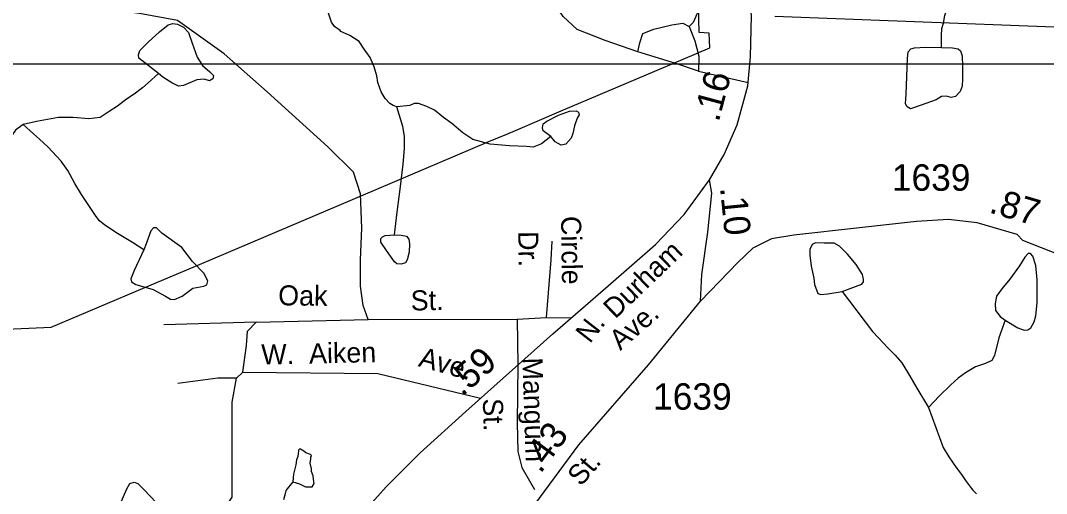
# Model space of a CAD drawing. Extents: x 2056842 to 2160602, y 826753 to 1016856.
# Drawn here: x 2090814 to 2095668, y 864586 to 866824 of the extents above; entities that cross this region are included whole.
import ezdxf

# ---------------------------------------------------------------- set-up
doc = ezdxf.new("R2010")
doc.units = 0
for name, color, linetype in [('Exist Boundary Political City Limit New', 7, 'Continuous'), ('Exist Hydrographic Creek Single Shore', 7, 'Continuous'), ('Exist Hydrographic Misc Water Feature', 7, 'Continuous'), ('Exist Road Non-System Type 51', 7, 'Continuous'), ('Exist Road Non-System Type 51 Label', 7, 'Continuous'), ('Exist Road Primary US Attributed', 7, 'Continuous'), ('Exist Road Primary US Label', 7, 'Continuous'), ('Exist Road Primary US Mileage Hundredths English Label', 7, 'Continuous'), ('Exist Road Secondary Mileage Hundredths English Label', 7, 'Continuous'), ('Exist Road Secondary Type 51 Attributed', 7, 'Continuous'), ('Exist Road Secondary Type 51 Label', 7, 'Continuous'), ('Exist Road Secondary Type 51 Number Label', 7, 'Continuous'), ('Map Preparation Boundary City Limit Buffer Line', 7, 'Continuous'), ('Scratch_Level_6', 7, 'Continuous')]:
    doc.layers.add(name, color=color, linetype=linetype)

msp = doc.modelspace()

# ---------------------------------------------------------------- linework, layer by layer
at = {"layer": 'Exist Boundary Political City Limit New'}
for points in [[(2090320.6, 865345.3), (2090958.1, 865372.4), (2091361.1, 865543.2), (2091671.4, 865674.6), (2092500, 866025.6), (2093030.2, 866250.8), (2093114.1, 866286.4), (2093155, 866303.8), (2093371.6, 866395.8), (2093866.6, 866606), (2093874.8, 866609.4), (2093886.4, 866614.4), (2094074.5, 866694.3), (2094071.5, 866763.2), (2094025.5, 866766.9), (2094021.9, 866891.5)], [(2094383.1, 866844.7), (2095704, 866794.2)]]:
    msp.add_lwpolyline(points, dxfattribs=at)
at = {"layer": 'Exist Hydrographic Creek Single Shore'}
for points in [[(2095170.7, 866696.3), (2095171.1, 866752.9), (2095173.2, 866785.1), (2095181, 866811.1), (2095186.9, 866847.1), (2095206.6, 866907), (2095216.4, 866935.2), (2095258.3, 866997.4), (2095282.3, 867031.5), (2095310.4, 867067.5), (2095335.8, 867103.6), (2095395.7, 867179.8), (2095415.3, 867223.9), (2095427.6, 867274), (2095437.1, 867316)], [(2092594.5, 866414.5), (2092576.4, 866421), (2092560.6, 866430.8), (2092538.3, 866454.9), (2092520.2, 866486.7), (2092504.2, 866530.6), (2092500.1, 866562.5), (2092487.6, 866604.5), (2092467.7, 866648.5), (2092439.6, 866688.5), (2092415.8, 866724.2), (2092371.6, 866752), (2092329.5, 866772.2), (2092325.4, 866776.1), (2092299.4, 866795.8), (2092285.2, 866815.7), (2092269, 866863.7)], [(2095170.7, 866696.3), (2095223, 866694.6), (2095250.9, 866689.7), (2095261.8, 866680), (2095269.1, 866655.7), (2095270.4, 866605.8), (2095271.6, 866547.5), (2095269.1, 866513.4), (2095259.4, 866487.9), (2095237.5, 866463.5), (2095216.9, 866459.9), (2095195, 866466), (2095170.7, 866464.8), (2095146.4, 866447.7), (2095074.7, 866423.4), (2095024.8, 866406.4), (2095009, 866414.9), (2095001.7, 866429.5), (2095004.2, 866474.5), (2095007.8, 866558.4), (2095010.2, 866646), (2095013.9, 866675.2), (2095026, 866689.7), (2095044.3, 866694.6), (2095096.5, 866697), (2095170.7, 866696.3)], [(2091466.5, 866572.6), (2091418.3, 866529.3), (2091390.4, 866505.1), (2091350.6, 866475), (2091314.7, 866450.9), (2091272.9, 866418.7), (2091232.7, 866392.6), (2091190.7, 866364.5), (2091136.7, 866358.3), (2091062.9, 866364.6), (2090993, 866364.6), (2090889.3, 866345.8), (2090826.8, 866332.1)], [(2090826.8, 866332.1), (2090790.5, 866304.6), (2090773.1, 866279.6), (2090763.1, 866253.3), (2090733.6, 866217.1), (2090693.4, 866192.8), (2090649.5, 866184.8), (2090601.5, 866174.7), (2090549.5, 866160.6), (2090485.7, 866142)], [(2095472.7, 865405.6), (2095532.2, 865369.4), (2095562.6, 865358.5), (2095579.6, 865360.9), (2095594.2, 865369.4), (2095610, 865398.6), (2095618.5, 865426.6), (2095623.4, 865488.6), (2095624.6, 865596.8), (2095617.3, 865664.9), (2095603.9, 865708.7), (2095591.8, 865720.9), (2095580.8, 865722.1), (2095566.3, 865703.8), (2095540.7, 865662.5), (2095494.5, 865599.3), (2095456.9, 865554.3), (2095431.3, 865519), (2095425.3, 865484.9), (2095427.7, 865452.1), (2095449.6, 865422.9), (2095472.7, 865405.6)], [(2094702.1, 865541.4), (2094845.3, 865352.1), (2094873.4, 865322.3), (2094917.9, 865274.6), (2094952.1, 865240.5), (2094983.9, 865204.4), (2095020.2, 865144.6), (2095054.5, 865085), (2095109.2, 864992.2)], [(2095472.7, 865405.6), (2095443.5, 865321.7), (2095422.8, 865239), (2095409.5, 865214.7), (2095379.1, 865201.3), (2095331.7, 865185.5), (2095285.5, 865157.6), (2095250.2, 865132), (2095215, 865100.4), (2095160.3, 865046.9), (2095109.2, 864992.2)], [(2095109.2, 864992.2), (2095179.3, 864803.2), (2095205.6, 864759.5), (2095241.5, 864709.4), (2095265.5, 864675.7), (2095285.5, 864647.9), (2095299.7, 864627.9), (2095314.1, 864609.9)], [(2095314.1, 864609.9), (2095320, 864601.7), (2095337.8, 864584.4)]]:
    msp.add_lwpolyline(points, dxfattribs=at)
at = {"layer": 'Exist Hydrographic Misc Water Feature'}
msp.add_line((2092102.1, 864641.5), (2092069.7, 864600.9), dxfattribs=at)
for points in [[(2091466.5, 866572.6), (2091374.1, 866645.1), (2091371.6, 866661.4), (2091377.8, 866681.4), (2091417.8, 866721.4), (2091471.5, 866770.1), (2091511.5, 866802.6), (2091534, 866810.1), (2091556.5, 866806.4), (2091585.2, 866792.6), (2091607.7, 866766.4), (2091626.4, 866716.4), (2091650.2, 866650.1), (2091673.9, 866610.1), (2091708.9, 866581.4), (2091726.4, 866563.9), (2091723.9, 866547.6), (2091707.7, 866537.6), (2091682.7, 866546.4), (2091647.7, 866542.6), (2091585.2, 866516.3), (2091561.5, 866512.6), (2091529, 866528.9), (2091486.5, 866555.1), (2091466.5, 866572.6)], [(2092582.4, 865810.4), (2092595.7, 865917.4), (2092610.3, 866025.6), (2092623.7, 866144.6), (2092629.8, 866217.5), (2092631, 866277.1), (2092622.5, 866322.1), (2092594.5, 866414.5)], [(2093322.6, 866274.7), (2093278.8, 866239.4), (2093239.1, 866224.9), (2093207.1, 866226.8), (2093127, 866230.5), (2093035.1, 866238.3), (2092953.1, 866260.1), (2092906.7, 866291.8), (2092854.7, 866335.9), (2092814.5, 866365.5), (2092772.6, 866399.5), (2092736.5, 866417.5), (2092696.4, 866431.3), (2092676.3, 866431.1), (2092656.4, 866421.1), (2092594.5, 866414.5)], [(2093322.6, 866274.7), (2093287.3, 866301.4), (2093283.7, 866316), (2093286.1, 866334.3), (2093304.3, 866347.7), (2093359, 866375.6), (2093411.3, 866395.1), (2093442.9, 866396.3), (2093453.8, 866390.2), (2093457.5, 866376.8), (2093447.7, 866361), (2093434.4, 866325.8), (2093427.1, 866289.3), (2093419.8, 866267.4), (2093393.1, 866238.2), (2093372.4, 866234.6), (2093343.2, 866250.4), (2093322.6, 866274.7)], [(2091396.5, 865739.1), (2091342.8, 865772.9), (2091272.8, 865815.4), (2091212.9, 865855.4), (2091186.6, 865876.6), (2091172.2, 865896.6), (2091140.2, 865944.5), (2091102.1, 866000.2), (2091069.9, 866052.1), (2091037.7, 866114.3), (2091005.5, 866158), (2090943.2, 866225.9), (2090903.4, 866261.6), (2090874.9, 866287.4), (2090826.8, 866332.1)], [(2091396.5, 865739.1), (2091351.6, 865641.6), (2091335.3, 865601.6), (2091339.1, 865587.8), (2091359.1, 865574.1), (2091441.5, 865551.6), (2091499, 865520.3), (2091522.7, 865505.3), (2091541.5, 865504.1), (2091577.7, 865520.3), (2091628.9, 865557.8), (2091681.4, 865566.6), (2091695.2, 865572.8), (2091700.2, 865591.6), (2091681.4, 865627.8), (2091627.7, 865684.1), (2091576.5, 865750.4), (2091482.8, 865817.9), (2091456.5, 865842.9), (2091442.8, 865842.9), (2091430.3, 865829.1), (2091407.8, 865767.9), (2091396.5, 865739.1)], [(2092582.4, 865810.4), (2092615.2, 865807.9), (2092639.5, 865803.1), (2092650.4, 865789.7), (2092654.1, 865767.8), (2092652.9, 865727.7), (2092643.1, 865691.2), (2092634.6, 865676.6), (2092614, 865671.7), (2092594.5, 865673), (2092582.4, 865682.7), (2092545.9, 865736.2), (2092519.2, 865775.1), (2092517.9, 865792.1), (2092526.4, 865800.6), (2092538.6, 865806.7), (2092582.4, 865810.4)], [(2094702.1, 865541.4), (2094764.1, 865565.7), (2094794.5, 865576.6), (2094801.7, 865587.6), (2094803, 865598.5), (2094796.9, 865621.6), (2094767.7, 865669.1), (2094726.4, 865717.7), (2094688.7, 865756.6), (2094663.2, 865770), (2094617, 865770), (2094575.7, 865772.4), (2094559.9, 865763.9), (2094547.7, 865740.8), (2094548.9, 865714.1), (2094555, 865661.8), (2094567.2, 865604.6), (2094570.8, 865575.4), (2094586.6, 865532.9), (2094601.2, 865526.8), (2094634, 865530.4), (2094702.1, 865541.4)], [(2092102.1, 864641.5), (2092134.1, 864631.7), (2092146.2, 864625.9), (2092162.2, 864617.7), (2092174.3, 864617.9), (2092194.2, 864617.8), (2092198.1, 864625.7), (2092202.4, 864634), (2092202, 864641.8), (2092198.1, 864669.9), (2092190.1, 864689.8), (2092189.9, 864702), (2092183.9, 864729.7), (2092187.6, 864749.8), (2092187.8, 864757.9), (2092189.9, 864765.7), (2092186, 864769.9), (2092163.8, 864777.7), (2092153.8, 864785.8), (2092137.6, 864795.6), (2092133.7, 864795.7), (2092129.6, 864791.5), (2092129.4, 864787.9), (2092127.7, 864775.5), (2092125.9, 864761.6), (2092119.7, 864745.4), (2092115.9, 864721.8), (2092106, 864677.4), (2092102.1, 864641.5)], [(2091385, 864514), (2091307.3, 864511.3), (2091288.9, 864515.3), (2091283.6, 864521.9), (2091284.9, 864535.1), (2091316.5, 864608.9), (2091331, 864632.6), (2091350.8, 864639.2), (2091367.9, 864633.9), (2091398.2, 864603.6), (2091454.9, 864543), (2091457.5, 864527.2), (2091445.7, 864519.2), (2091418, 864516.6), (2091385, 864514)], [(2092069.7, 864600.9), (2092067.7, 864591), (2092058.2, 864556.8)]]:
    msp.add_lwpolyline(points, dxfattribs=at)
at = {"layer": 'Exist Road Non-System Type 51'}
for p, q in [((2094020.9, 866584.5), (2094256.2, 866530.3)), ((2091928.4, 865397), (2091492.3, 865384.5)), ((2091928.4, 865397), (2092458.4, 865409.4)), ((2092458.4, 865409.4), (2093163.2, 865410.5)), ((2093163.2, 865410.5), (2093302.4, 865418.8)), ((2093163.2, 865410.5), (2093166.7, 865194.5)), ((2093302.4, 865418.8), (2093419.7, 865417.4)), ((2091835, 865130.9), (2091866.1, 865160))]:
    msp.add_line(p, q, dxfattribs=at)
for points in [[(2093733.9, 866675.8), (2093580, 866729), (2093447, 866780.4), (2093380.5, 866843.1), (2093343.5, 866897.3), (2093313, 866944.9), (2093276.9, 867013.3), (2093210.4, 867098.9), (2093130.6, 867245.3), (2093042.3, 867360.3), (2092783.8, 867643.7), (2092717.3, 867698.8), (2092588.1, 867860.4), (2092466.5, 867949.8), (2092256.5, 868034.4), (2091990.5, 868125.7), (2091804.3, 868226.5), (2091699.8, 868293), (2091504, 868547.8), (2091463.2, 868571.6), (2091261.8, 868615.3)], [(2092458.4, 865409.4), (2092434.2, 865474.9), (2092421.7, 865566.4), (2092421.7, 865691.1), (2092428, 865840.7), (2092422.8, 866003.9), (2092389.5, 866105.7), (2092267, 866226.3), (2091980.4, 866486.1), (2091777.8, 866665.9), (2091555.6, 866823.8), (2091377, 866857.1), (2091277.3, 866869.5), (2091173.4, 866917.3), (2091107, 866985.9), (2091046.7, 867081.5), (2090984.4, 867218.7)], [(2094269, 866877.3), (2094233.7, 866875.4), (2094159.6, 866886.9), (2094072.2, 866907.8), (2094032.3, 866896.4), (2093996.2, 866814.6), (2093977.2, 866795.6)], [(2093733.9, 866675.8), (2093743.4, 866717.6), (2093758.6, 866761.4), (2093810, 866782.3), (2093895.5, 866803.2), (2093946.8, 866810.8), (2093977.2, 866795.6)], [(2093977.2, 866795.6), (2094003.8, 866727.1), (2094022.8, 866654.9), (2094020.9, 866584.5)], [(2094020.9, 866584.5), (2093914.5, 866620.6), (2093733.9, 866675.8)], [(2093302.4, 865418.8), (2093325.2, 865691.1), (2093329.4, 865780.4)], [(2091866.1, 865160), (2091882.7, 865286.8), (2091886.9, 865353.3), (2091928.4, 865397)], [(2093166.7, 865194.5), (2093163.4, 864920.1), (2093166.1, 864784.7), (2093185, 864709), (2093246.2, 864605.7)], [(2091866.1, 865160), (2092503.8, 865153.8), (2092990.2, 865037.5)], [(2091835, 865130.9), (2091747.7, 865130.9), (2091558.7, 865106)], [(2091595.1, 864493.9), (2091782, 864518.8), (2091815.2, 864568.7), (2091815.2, 865017.7), (2091835, 865130.9)]]:
    msp.add_lwpolyline(points, dxfattribs=at)
at = {"layer": 'Exist Road Primary US Attributed'}
for points in [[(2094073.2, 866070.1), (2094143.5, 866189.9), (2094205.3, 866329.7), (2094254.7, 866514.1), (2094268, 866651), (2094271.8, 866845), (2094219.5, 867465.8), (2094206.2, 867669.2), (2094179.6, 867992.5)], [(2091871.9, 863872), (2092073.9, 864092.9), (2092544.4, 864617.6), (2092704.3, 864777.7), (2092921.1, 864973.9), (2093332.5, 865342), (2093594.2, 865568.5), (2093818.5, 865763.9), (2093953.5, 865905.2), (2094073.2, 866070.1)]]:
    msp.add_lwpolyline(points, dxfattribs=at)
at = {"layer": 'Exist Road Secondary Type 51 Attributed'}
for points in [[(2094030.9, 865495.2), (2094037.6, 865622.5), (2094065.7, 865822), (2094084.9, 866006.5), (2094073.2, 866070.1)], [(2095997.7, 865609.5), (2095556.9, 865783.6), (2095529.9, 865810.6), (2095339.9, 865866.7), (2095204.3, 865881.8), (2095052.7, 865873.5), (2094782.7, 865843.3), (2094472.8, 865808.5), (2094366.8, 865790.8), (2094278.6, 865747.2), (2094208, 865679.6), (2094030.9, 865495.2)], [(2092795.1, 863628.8), (2092828.4, 863700.5), (2092903.7, 863934.9), (2092988.8, 864114.7), (2093061, 864248.2), (2093246.7, 864534.1), (2093454.6, 864816.6), (2093784.8, 865194.9), (2094030.9, 865495.2)]]:
    msp.add_lwpolyline(points, dxfattribs=at)
at = {"layer": 'Map Preparation Boundary City Limit Buffer Line'}
for points in [[(2090320.6, 865345.3), (2090958.1, 865372.4), (2091361.1, 865543.2), (2091671.4, 865674.6), (2092500, 866025.6), (2093030.2, 866250.8), (2093114.1, 866286.4), (2093155, 866303.8), (2093371.6, 866395.8), (2093866.6, 866606), (2093874.8, 866609.4), (2093886.4, 866614.4), (2094074.5, 866694.3), (2094071.5, 866763.2), (2094025.5, 866766.9), (2094021.9, 866891.5)], [(2094383.1, 866844.7), (2095704, 866794.2)]]:
    msp.add_lwpolyline(points, dxfattribs=at)
at = {"layer": 'Scratch_Level_6'}
msp.add_lwpolyline([(2086659.3, 866617.9), (2097771.9, 866617.9), (2097771.9, 859318.2), (2086659.3, 859318.2)], close=True, dxfattribs=at)

# ---------------------------------------------------------------- texts
at = {"layer": 'Exist Road Non-System Type 51 Label'}
for s, rotation, p in [('Circle', 270.8419, (2093371.1, 865898.1)), ('Dr.', 270.8419, (2093168.3, 865826.5)), ('Oak', 359.3185, (2092032.4, 865476.3)), ('St.', 1.2171, (2092660.9, 865451.3)), ('W.  Aiken', 1.2277, (2091954, 865195.9)), ('Ave.', 344.5451, (2092692, 865188.8)), ('Mangum', 271.7919, (2093188.3, 865227.9)), ('St.', 271.7919, (2093000.8, 865035.1))]:
    msp.add_text(s, height=95, rotation=rotation, dxfattribs=at).set_placement(p)
at = {"layer": 'Exist Road Primary US Label'}
for s, rotation, p in [('Durham', 43.8609, (2093627.5, 865408.5)), ('Ave.', 41.1136, (2093651.6, 865259.8)), ('N.', 52.2022, (2093507.7, 865292.1))]:
    msp.add_text(s, height=95, rotation=rotation, dxfattribs=at).set_placement(p)
at = {"layer": 'Exist Road Primary US Mileage Hundredths English Label'}
for s, rotation, p in [('.16', 75.0047, (2094116.7, 866339.4)), ('.59', 41.8148, (2092903, 865041.6))]:
    msp.add_text(s, height=125, rotation=rotation, dxfattribs=at).set_placement(p)
at = {"layer": 'Exist Road Secondary Mileage Hundredths English Label'}
for s, rotation, p in [('.10', 275.7412, (2094123.2, 866032.6)), ('.87', 343.5488, (2095391.7, 865916.6)), ('.43', 53.6675, (2093273.7, 864676.2))]:
    msp.add_text(s, height=125, rotation=rotation, dxfattribs=at).set_placement(p)
at = {"layer": 'Exist Road Secondary Type 51 Label'}
msp.add_text('St.', height=95, rotation=49.4453, dxfattribs=at).set_placement((2093465.3, 864616.1))
at = {"layer": 'Exist Road Secondary Type 51 Number Label'}
for p in [(2094936.6, 866018.3), (2093806.7, 864982.6)]:
    msp.add_text('1639', height=125, dxfattribs=at).set_placement(p)

doc.saveas('drawing.dxf')
